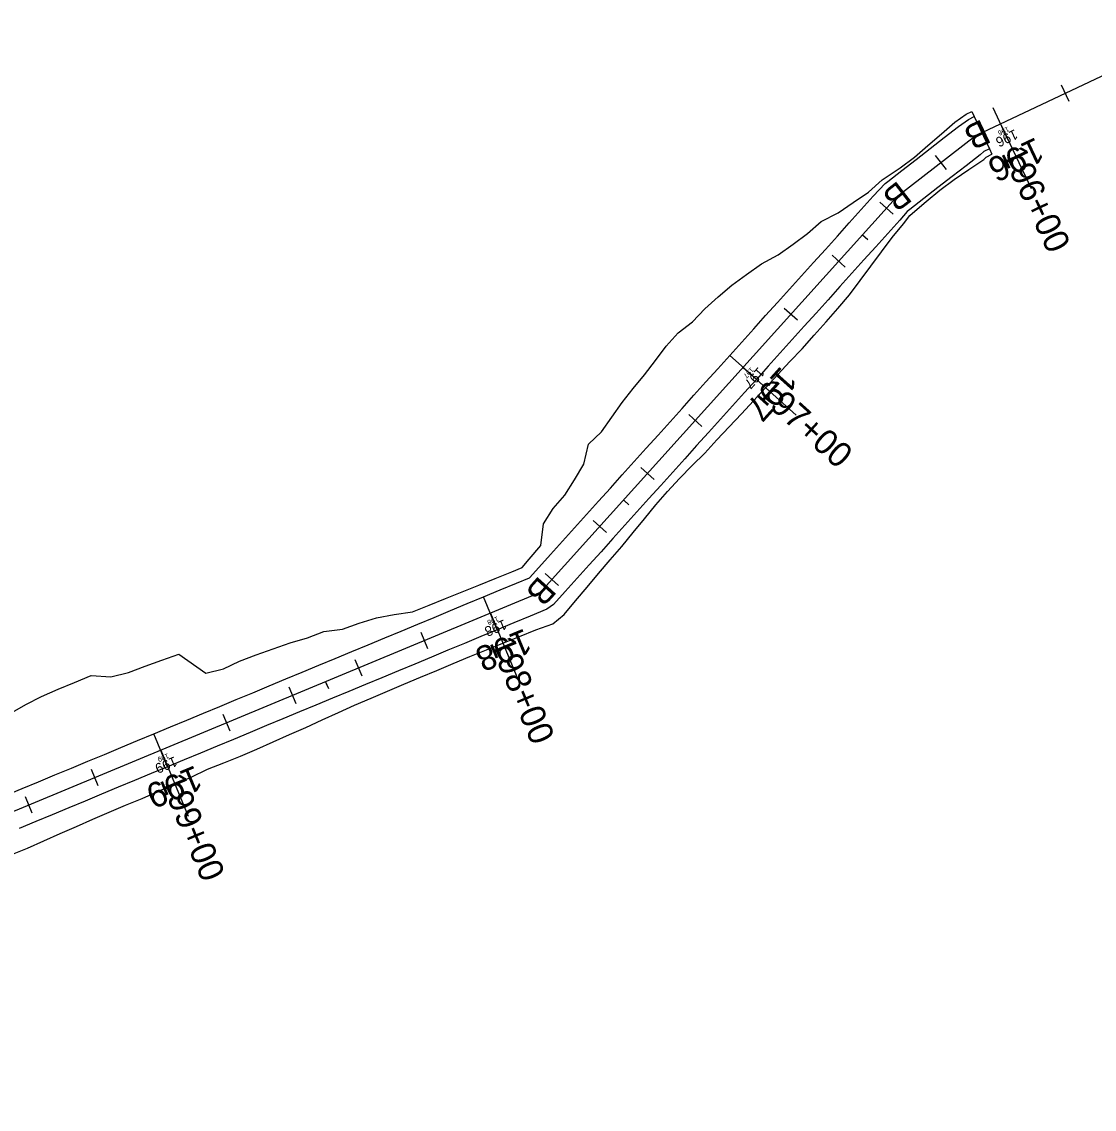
# Model space of a CAD drawing. Extents: x 1823824 to 1861612, y 706975 to 726130.
# Drawn here: x 1825501.4 to 1825801.7, y 712478.5 to 712783.1 of the extents above; entities that cross this region are included whole.
import ezdxf

# ---------------------------------------------------------------- set-up
doc = ezdxf.new("R2010")
doc.units = 0
for name, color, linetype in [('DR_X_Flood_Boundary', 7, 'Continuous'), ('GE_X_CL_10', 7, 'Continuous'), ('GE_X_CL_100', 7, 'Continuous'), ('GE_X_CL_20', 7, 'Continuous'), ('GE_X_CL_200', 7, 'Continuous'), ('GE_X_CL_50', 7, 'Continuous'), ('SC_Scratch1', 7, 'Continuous'), ('SC_Scratch2', 7, 'Continuous'), ('SC_Scratch5', 7, 'Continuous'), ('SC_Scratch6', 7, 'Continuous')]:
    doc.layers.add(name, color=color, linetype=linetype)

msp = doc.modelspace()

# ---------------------------------------------------------------- linework, layer by layer
at = {"layer": 'DR_X_Flood_Boundary'}
for p, q in [((1825836.12, 712783.15), (1825768.62, 712751.29)), ((1825768.62, 712751.29), (1825746.23, 712733.9)), ((1825746.23, 712733.9), (1825646.54, 712623.21)), ((1825646.54, 712623.21), (1825298.33, 712478.48))]:
    msp.add_line(p, q, dxfattribs=at)
at = {"layer": 'GE_X_CL_10'}
for p, q in [((1825775.51, 712754.54), (1825775.94, 712753.64)), ((1825736.84, 712723.47), (1825737.58, 712722.81)), ((1825703.38, 712686.32), (1825704.12, 712685.65)), ((1825669.92, 712649.17), (1825670.66, 712648.5)), ((1825632.63, 712617.43), (1825633.01, 712616.51)), ((1825586.46, 712598.24), (1825586.84, 712597.32)), ((1825540.28, 712579.05), (1825540.67, 712578.13))]:
    msp.add_line(p, q, dxfattribs=at)
at = {"layer": 'GE_X_CL_100'}
for p, q in [((1825775.51, 712754.54), (1825779.78, 712745.5)), ((1825703.38, 712686.32), (1825710.81, 712679.63)), ((1825632.63, 712617.43), (1825636.46, 712608.2)), ((1825540.28, 712579.05), (1825544.12, 712569.81))]:
    msp.add_line(p, q, dxfattribs=at)
at = {"layer": 'GE_X_CL_20'}
for p, q in [((1825775.51, 712754.54), (1825776.36, 712752.73)), ((1825736.84, 712723.47), (1825738.33, 712722.14)), ((1825703.38, 712686.32), (1825704.87, 712684.98)), ((1825669.92, 712649.17), (1825671.4, 712647.83)), ((1825632.63, 712617.43), (1825633.39, 712615.58)), ((1825586.46, 712598.24), (1825587.22, 712596.39)), ((1825540.28, 712579.05), (1825541.05, 712577.2))]:
    msp.add_line(p, q, dxfattribs=at)
at = {"layer": 'GE_X_CL_200'}
for p, q in [((1825775.51, 712754.54), (1825784.05, 712736.46)), ((1825703.38, 712686.32), (1825718.24, 712672.94)), ((1825632.63, 712617.43), (1825640.3, 712598.96)), ((1825540.28, 712579.05), (1825547.96, 712560.58))]:
    msp.add_line(p, q, dxfattribs=at)
at = {"layer": 'GE_X_CL_50'}
for p, q in [((1825775.51, 712754.54), (1825777.65, 712750.02)), ((1825703.38, 712686.32), (1825707.1, 712682.98)), ((1825632.63, 712617.43), (1825634.55, 712612.81)), ((1825540.28, 712579.05), (1825542.2, 712574.43))]:
    msp.add_line(p, q, dxfattribs=at)
at = {"layer": 'SC_Scratch1'}
msp.add_lwpolyline([(1825767.42, 712757.99), (1825768.09, 712756.57), (1825772.36, 712747.53), (1825773.08, 712746.01)], dxfattribs=at)
at = {"layer": 'SC_Scratch2'}
for points in [[(1825641.55, 712630.27), (1825643.5, 712632.58), (1825646.72, 712636.41), (1825647.44, 712642.49), (1825650.19, 712646.75), (1825653.48, 712650.51), (1825656.17, 712654.82), (1825658.74, 712659.23), (1825660.05, 712664.78), (1825663.68, 712668.24), (1825666.58, 712672.36), (1825669.52, 712676.44), (1825672.57, 712680.42), (1825675.8, 712684.24), (1825678.81, 712688.26), (1825681.83, 712692.27), (1825685.15, 712696.01), (1825689.19, 712699.1), (1825692.62, 712702.74), (1825696.36, 712706.1), (1825700.24, 712709.33), (1825704.38, 712712.34), (1825708.5, 712715.35), (1825713.16, 712717.88), (1825717.37, 712720.82), (1825721.46, 712723.87), (1825725.26, 712727.17), (1825729.99, 712729.65), (1825734.23, 712732.55), (1825738.49, 712735.44), (1825742.36, 712738.88), (1825743.17, 712739.42), (1825747.33, 712742.22), (1825751.35, 712745.18), (1825755.14, 712748.46), (1825758.94, 712751.72), (1825762.73, 712754.99), (1825765.82, 712757.24), (1825767.42, 712757.99)], [(1825643.58, 712627.4), (1825646.13, 712630.22), (1825649.47, 712633.94), (1825652.82, 712637.65), (1825656.16, 712641.37), (1825659.51, 712645.08), (1825662.86, 712648.8), (1825666.2, 712652.51), (1825669.55, 712656.23), (1825672.89, 712659.94), (1825676.24, 712663.66), (1825679.59, 712667.37), (1825682.93, 712671.09), (1825686.28, 712674.81), (1825689.63, 712678.52), (1825692.97, 712682.24), (1825696.32, 712685.95), (1825699.66, 712689.67), (1825703.01, 712693.38), (1825706.36, 712697.1), (1825709.7, 712700.81), (1825713.05, 712704.53), (1825716.39, 712708.24), (1825719.74, 712711.96), (1825723.09, 712715.67), (1825726.43, 712719.39), (1825729.78, 712723.1), (1825733.12, 712726.82), (1825736.47, 712730.53), (1825739.82, 712734.25), (1825743.16, 712737.85), (1825743.93, 712738.44), (1825747.88, 712741.51), (1825751.83, 712744.58), (1825755.77, 712747.64), (1825759.72, 712750.71), (1825763.67, 712753.78), (1825766.49, 712755.81), (1825768.09, 712756.57)], [(1825772.36, 712747.53), (1825770.76, 712746.77), (1825769.81, 712745.88), (1825765.86, 712742.81), (1825761.91, 712739.75), (1825757.96, 712736.68), (1825754.01, 712733.61), (1825750.06, 712730.54), (1825749.3, 712729.95), (1825747.25, 712727.56), (1825743.9, 712723.84), (1825740.56, 712720.13), (1825737.21, 712716.41), (1825733.86, 712712.7), (1825730.52, 712708.98), (1825727.17, 712705.27), (1825723.82, 712701.55), (1825720.48, 712697.84), (1825717.13, 712694.12), (1825713.79, 712690.4), (1825710.44, 712686.69), (1825707.09, 712682.97), (1825703.75, 712679.26), (1825700.4, 712675.54), (1825697.06, 712671.83), (1825693.71, 712668.11), (1825690.36, 712664.4), (1825687.02, 712660.68), (1825683.67, 712656.97), (1825680.33, 712653.25), (1825676.98, 712649.54), (1825673.63, 712645.82), (1825670.29, 712642.11), (1825666.94, 712638.39), (1825663.59, 712634.68), (1825660.25, 712630.96), (1825656.9, 712627.24), (1825653.56, 712623.53), (1825650.26, 712619.87), (1825648.4, 712618.57), (1825643.78, 712616.65), (1825639.16, 712614.73), (1825634.54, 712612.81), (1825629.93, 712610.89), (1825625.31, 712608.97), (1825620.69, 712607.06), (1825616.08, 712605.14), (1825611.46, 712603.22), (1825606.84, 712601.3), (1825602.22, 712599.38), (1825597.61, 712597.46), (1825592.99, 712595.54), (1825588.37, 712593.62), (1825583.76, 712591.7), (1825579.14, 712589.78), (1825574.52, 712587.86), (1825569.91, 712585.95), (1825565.29, 712584.03), (1825560.67, 712582.11), (1825556.05, 712580.19), (1825551.44, 712578.27), (1825546.82, 712576.35), (1825542.2, 712574.43), (1825537.59, 712572.51), (1825532.97, 712570.59), (1825528.35, 712568.67), (1825523.73, 712566.76), (1825519.12, 712564.84), (1825514.5, 712562.92), (1825509.88, 712561), (1825505.27, 712559.08), (1825500.65, 712557.16)], [(1825548.83, 712571.52), (1825553.33, 712573.72), (1825557.99, 712575.53), (1825562.63, 712577.39), (1825567.21, 712579.4), (1825571.78, 712581.43), (1825576.36, 712583.45), (1825580.93, 712585.47), (1825585.49, 712587.54), (1825590.04, 712589.62), (1825594.59, 712591.69), (1825599.18, 712593.67), (1825603.79, 712595.61), (1825608.4, 712597.55), (1825613, 712599.5), (1825617.62, 712601.43), (1825622.22, 712603.37), (1825626.84, 712605.29), (1825631.47, 712607.17), (1825636.09, 712609.08), (1825640.73, 712610.95), (1825645.37, 712612.83), (1825650.11, 712614.45), (1825653.31, 712617.12), (1825656.43, 712620.94), (1825659.68, 712624.74), (1825662.92, 712628.55), (1825666.16, 712632.36), (1825669.4, 712636.18), (1825672.6, 712640.02), (1825675.75, 712643.92), (1825678.9, 712647.81), (1825682.22, 712651.55), (1825685.61, 712655.22), (1825689.11, 712658.8), (1825692.66, 712662.33), (1825696.07, 712665.98), (1825699.51, 712669.62), (1825702.92, 712673.28), (1825706.3, 712676.96), (1825709.7, 712680.63), (1825713.07, 712684.32), (1825716.5, 712687.96), (1825719.97, 712691.56), (1825723.29, 712695.3), (1825726.61, 712699.04), (1825729.93, 712702.78), (1825733.15, 712706.61), (1825736.15, 712710.64), (1825739.15, 712714.66), (1825742.16, 712718.69), (1825745.17, 712722.7), (1825748.34, 712726.58), (1825750.11, 712728.9), (1825750.85, 712729.53), (1825754.68, 712732.75), (1825758.48, 712736), (1825762.5, 712738.98), (1825766.65, 712741.79), (1825770.8, 712744.59), (1825771.48, 712745.24), (1825773.08, 712746.01)], [(1825506.93, 712594.15), (1825511.52, 712596.14), (1825516.14, 712598.06), (1825520.75, 712599.99), (1825526.3, 712599.67), (1825531.23, 712600.84), (1825535.9, 712602.62), (1825540.63, 712604.28), (1825545.35, 712605.95), (1825552.95, 712600.69), (1825557.86, 712601.91), (1825562.38, 712604.04), (1825567.05, 712605.83), (1825571.77, 712607.51), (1825576.49, 712609.18), (1825581.35, 712610.51), (1825586, 712612.35), (1825591.17, 712612.95), (1825595.89, 712614.63), (1825600.67, 712616.16), (1825605.69, 712617.11), (1825610.81, 712617.8), (1825615.45, 712619.67), (1825620.07, 712621.57), (1825624.7, 712623.48), (1825629.34, 712625.33), (1825633.98, 712627.2), (1825638.61, 712629.08), (1825641.55, 712630.27)], [(1825515.28, 712574.07), (1825519.9, 712575.99), (1825524.51, 712577.91), (1825529.13, 712579.83), (1825533.75, 712581.75), (1825538.36, 712583.67), (1825542.98, 712585.58), (1825547.6, 712587.5), (1825552.22, 712589.42), (1825556.83, 712591.34), (1825561.45, 712593.26), (1825566.07, 712595.18), (1825570.68, 712597.1), (1825575.3, 712599.02), (1825579.92, 712600.94), (1825584.54, 712602.86), (1825589.15, 712604.77), (1825593.77, 712606.69), (1825598.39, 712608.61), (1825603, 712610.53), (1825607.62, 712612.45), (1825612.24, 712614.37), (1825616.85, 712616.29), (1825621.47, 712618.21), (1825626.09, 712620.13), (1825630.71, 712622.05), (1825635.32, 712623.97), (1825639.94, 712625.88), (1825643.58, 712627.4)], [(1825498.1, 712589.34), (1825502.47, 712591.87), (1825506.93, 712594.15)], [(1825496.81, 712566.39), (1825501.43, 712568.31), (1825506.05, 712570.23), (1825510.66, 712572.15), (1825515.28, 712574.07)], [(1825498.33, 712549.72), (1825502.95, 712551.63), (1825507.53, 712553.64), (1825512.09, 712555.7), (1825516.65, 712557.74), (1825521.23, 712559.76), (1825525.82, 712561.74), (1825530.43, 712563.68), (1825535.06, 712565.57), (1825539.65, 712567.55), (1825544.24, 712569.53), (1825548.83, 712571.52)]]:
    msp.add_lwpolyline(points, dxfattribs=at)
at = {"layer": 'SC_Scratch5'}
for points in [[(1825794.66, 712760.82), (1825792.53, 712765.34)], [(1825777.65, 712750.02), (1825773.38, 712759.06)], [(1825760.38, 712741.72), (1825757.31, 712745.67)], [(1825745.39, 712729.23), (1825741.68, 712732.58)], [(1825732.01, 712714.37), (1825728.29, 712717.72)], [(1825718.62, 712699.51), (1825714.91, 712702.86)], [(1825707.1, 712682.98), (1825699.66, 712689.67)], [(1825691.85, 712669.79), (1825688.14, 712673.13)], [(1825678.47, 712654.93), (1825674.75, 712658.27)], [(1825665.08, 712640.06), (1825661.37, 712643.41)], [(1825651.7, 712625.2), (1825647.98, 712628.55)], [(1825634.55, 712612.81), (1825630.71, 712622.05)], [(1825615.12, 712607.45), (1825613.2, 712612.06)], [(1825596.65, 712599.77), (1825594.73, 712604.39)], [(1825578.18, 712592.09), (1825576.26, 712596.71)], [(1825559.71, 712584.42), (1825557.79, 712589.03)], [(1825542.2, 712574.43), (1825538.37, 712583.67)], [(1825522.78, 712569.06), (1825520.86, 712573.68)], [(1825504.31, 712561.39), (1825502.39, 712566.01)]]:
    msp.add_lwpolyline(points, dxfattribs=at)

# ---------------------------------------------------------------- texts
at = {"layer": 'GE_X_CL_10'}
for s, rotation, p in [('196', 205.2686, (1825777.5, 712753.82)), ('197', 227.9926, (1825705.51, 712686.44)), ('198', 202.5699, (1825634.55, 712616.6)), ('199', 202.5699, (1825542.22, 712578.23))]:
    msp.add_text(s, height=1.4, rotation=rotation, dxfattribs=at).set_placement(p)
at = {"layer": 'GE_X_CL_20'}
for s, rotation, p in [('196', 205.2686, (1825779.48, 712753.1)), ('197', 227.9926, (1825707.64, 712686.57)), ('198', 202.5699, (1825636.46, 712615.78)), ('199', 202.5699, (1825544.16, 712577.41))]:
    msp.add_text(s, height=2.8, rotation=rotation, dxfattribs=at).set_placement(p)
at = {"layer": 'GE_X_CL_50'}
for s, rotation, p in [('196', 205.2686, (1825785.44, 712750.94)), ('197', 227.9926, (1825714.02, 712686.93)), ('198', 202.5699, (1825642.22, 712613.3)), ('199', 202.5699, (1825549.98, 712574.96))]:
    msp.add_text(s, height=7, rotation=rotation, dxfattribs=at).set_placement(p)
at = {"layer": 'SC_Scratch5'}
for s, rotation, p in [('196+00', 295.2686, (1825775.55, 712746.27)), ('197+00', 317.9926, (1825706.61, 712678.7)), ('198+00', 292.5699, (1825632.27, 712609.16)), ('199+00', 292.5699, (1825539.93, 712570.78))]:
    msp.add_text(s, height=7, rotation=rotation, dxfattribs=at).set_placement(p)
at = {"layer": 'SC_Scratch6'}
for rotation, p in [(205.2686, (1825770.29, 712755.95)), (217.8363, (1825746.85, 712738.81)), (227.9926, (1825646.29, 712628.16))]:
    msp.add_text('B', height=7, rotation=rotation, dxfattribs=at).set_placement(p)

doc.saveas('drawing.dxf')
